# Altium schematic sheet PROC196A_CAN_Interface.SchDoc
size 431 x 279 mm; Date: Not shown in title block; ApprovedBy: Not shown in title block; CheckedBy: Not shown in title block; Author: Not shown in title block; CompanyName: Not shown in title block; Engineer: Not shown in title block; Organization: Not shown in title block; Address1: Not shown in title block; Address2: Not shown in title block; Address3: Not shown in title block; Address4: Not shown in title block; DocumentNumber: 22; Revision: Use project parameter SCH_Rev; SheetNumber: 22; SheetTotal: 25; PageSetup: Record=PageOptions¦CenterHorizontal=True¦CenterVertical=True¦PrintScale=1.00¦XCorrection=1.00¦YCorrection=1.00¦PrintKind=0¦BorderSize=5000000¦LeftOffset=0¦BottomOffset=0¦Orientation=2¦PaperLength=1000¦PaperWidth=1000¦Scale=100¦PaperSource=15¦PrintQuality=600¦MediaType=1¦DitherType=10¦PaperKind=Letter¦PrintScaleMode=1
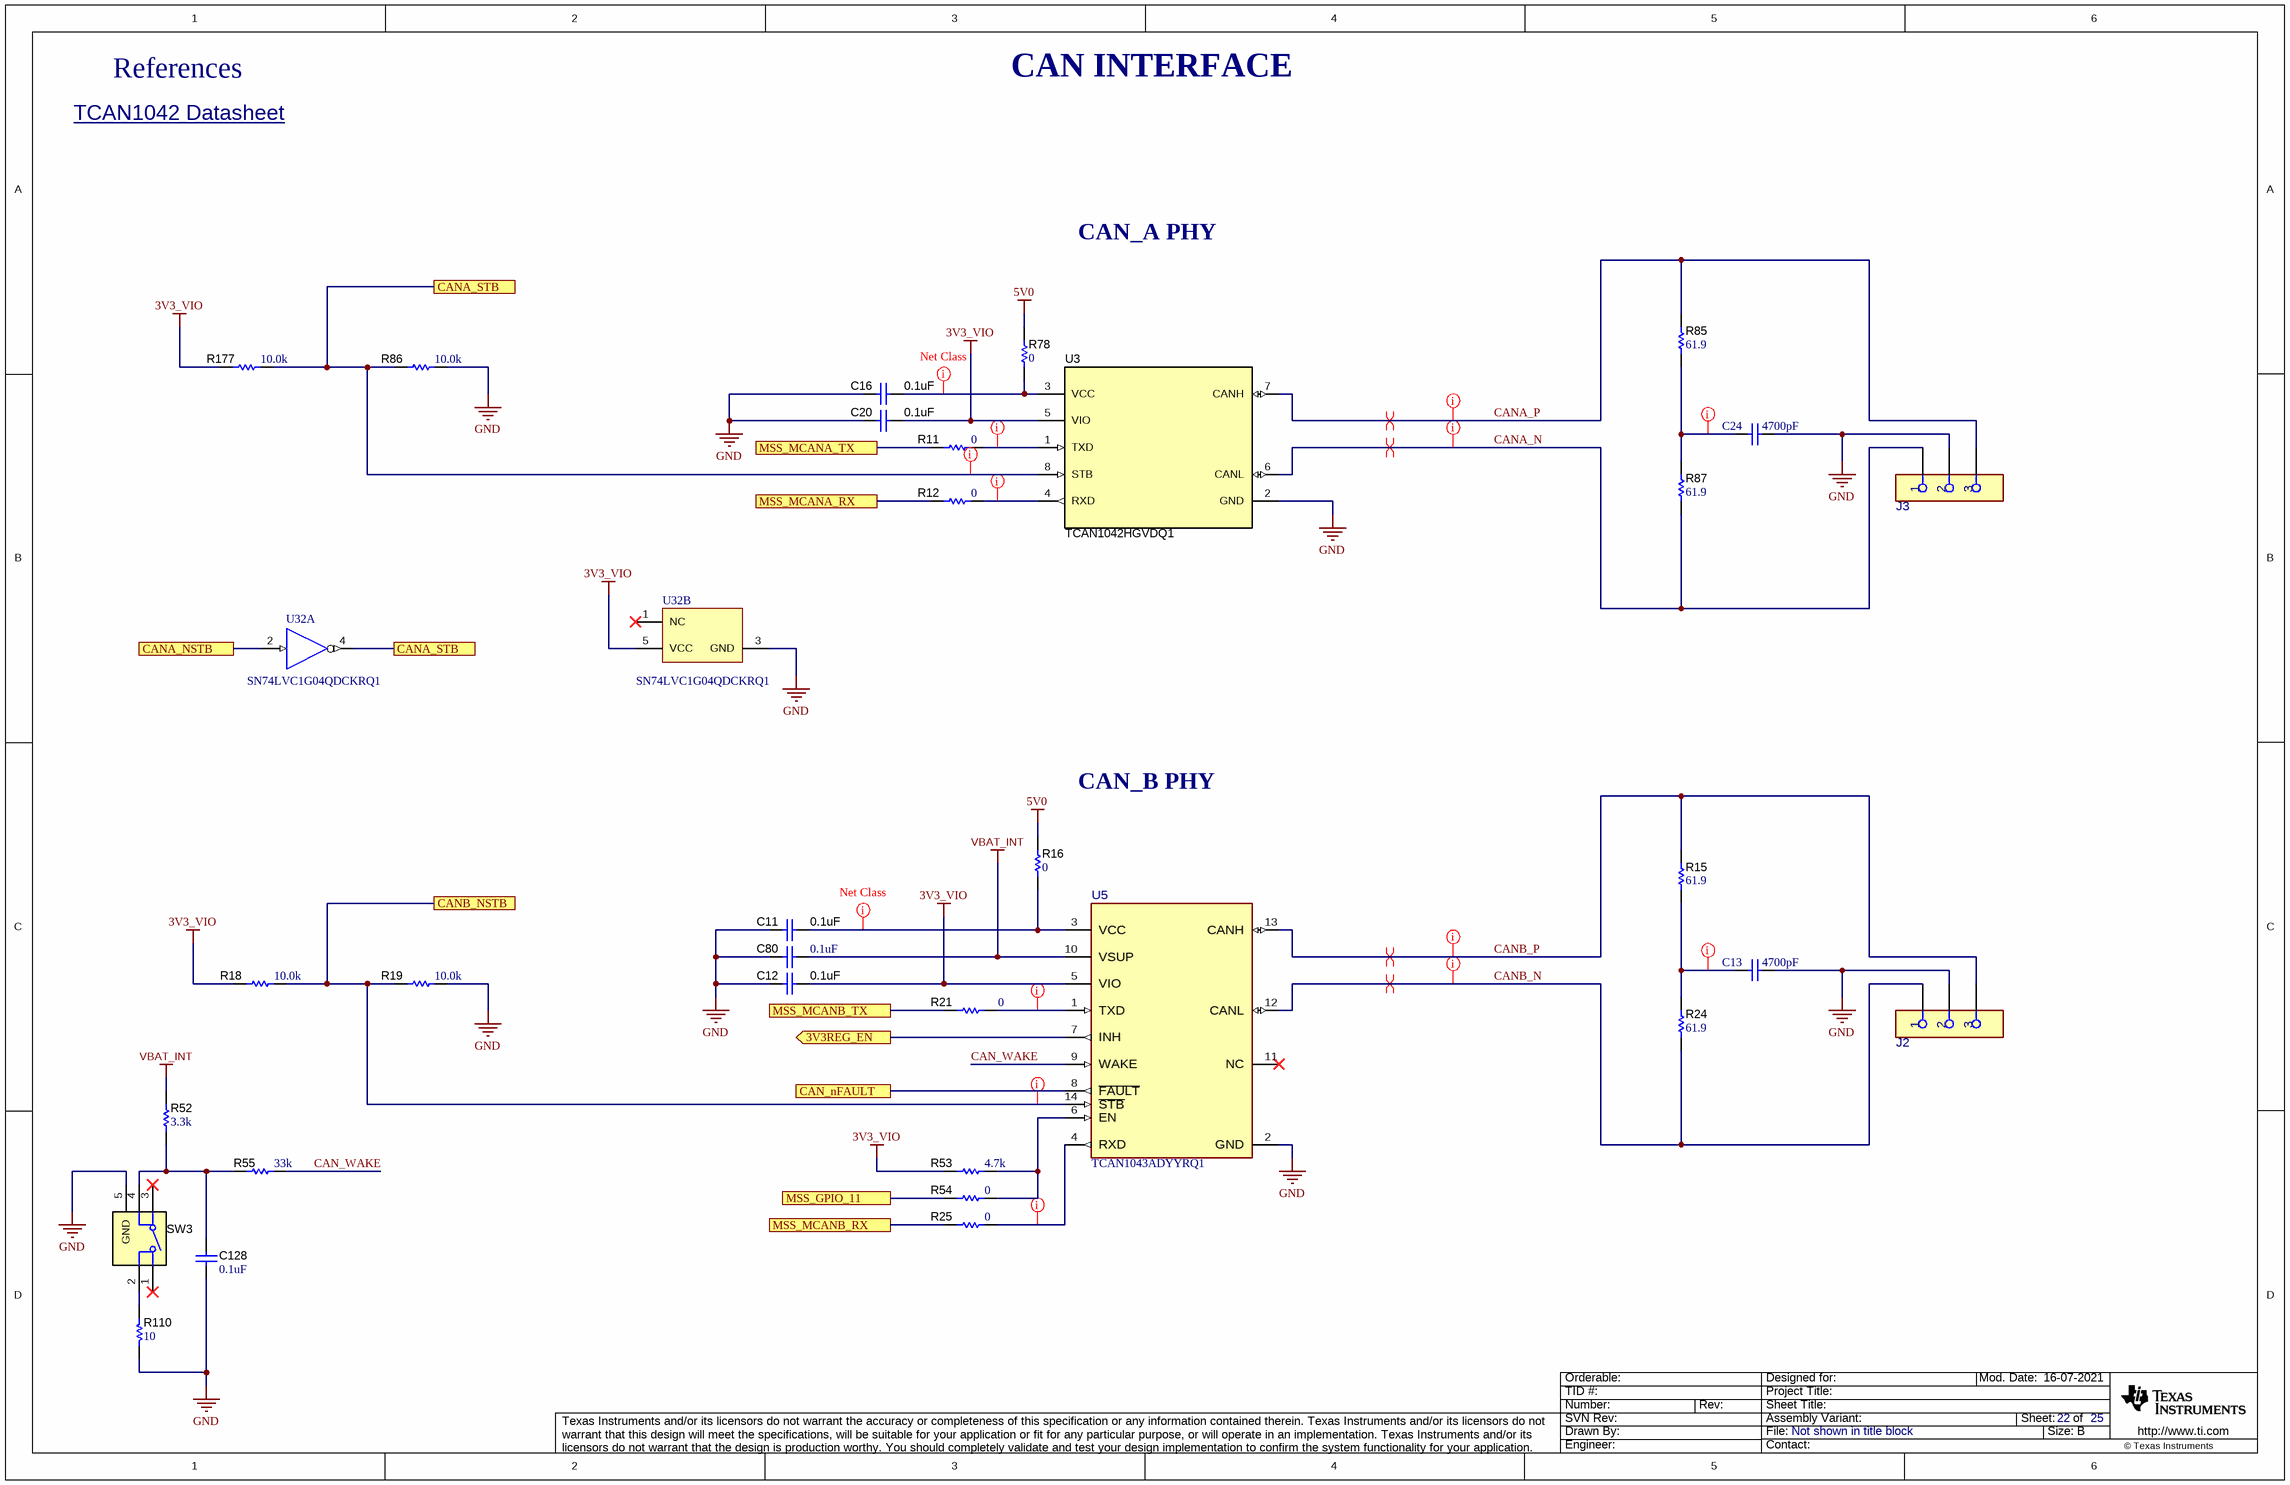
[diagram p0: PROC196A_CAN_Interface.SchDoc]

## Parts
C11  ValueDisplayed: 0.1uF  [0402L]  (hidden comment: GCM155R71C104KA55D)
C12  ValueDisplayed: 0.1uF  [0402L]  (hidden comment: GCM155R71C104KA55D)
C13  ValueDisplayed: 4700pF  [0402L]  (hidden comment: GCM155R71H472KA37D)
C16  ValueDisplayed: 0.1uF  [0402L]  (hidden comment: GCM155R71C104KA55D)
C20  ValueDisplayed: 0.1uF  [0402L]  (hidden comment: GCM155R71C104KA55D)
C24  ValueDisplayed: 4700pF  [0402L]  (hidden comment: GCM155R71H472KA37D)
C80  ValueDisplayed: 0.1uF  [0402L]  (hidden comment: CGA2B3X7R1H104K050BB)
C128  ValueDisplayed: 0.1uF  [0402L]  (hidden comment: CGA2B3X7R1H104K050BB)
J2  OSTTF030161  [FP-OSTTF030161_PTH_TERMINAL_BLOCK-MFG]  (value not drawn)
J3  OSTTF030161  [FP-OSTTF030161_PTH_TERMINAL_BLOCK-MFG]  (value not drawn)
R11  value 0  [0402L]  (hidden comment: ERJ-2GE0R00X)
R12  ValueDisplayed: 0  [0402L]  (hidden comment: ERJ-2GE0R00X)
R15  ValueDisplayed: 61.9  [0402L]  (hidden comment: CRCW040261R9FKED)
R16  ValueDisplayed: 0  [0402L]  (hidden comment: ERJ-2GE0R00X)
R18  ValueDisplayed: 10.0k  [0402L]  (hidden comment: CRCW040210K0FKED)
R19  ValueDisplayed: 10.0k  [0402L]  (hidden comment: CRCW040210K0FKED)
R21  value 0  [0402L]  (hidden comment: ERJ-2GE0R00X)
R24  ValueDisplayed: 61.9  [0402L]  (hidden comment: CRCW040261R9FKED)
R25  ValueDisplayed: 0  [0402L]  (hidden comment: ERJ-2GE0R00X)
R52  ValueDisplayed: 3.3k  [0402L]  (hidden comment: CRCW04023K30JNED)
R53  ValueDisplayed: 4.7k  [0402L]  (hidden comment: CRCW04024K70JNED)
R54  ValueDisplayed: 0  [0402L]  (hidden comment: ERJ-2GE0R00X)
R55  ValueDisplayed: 33k  [0402L]  (hidden comment: CRCW040233K0JNED)
R78  ValueDisplayed: 0  [0402L]  (hidden comment: ERJ-2GE0R00X)
R85  ValueDisplayed: 61.9  [0402L]  (hidden comment: CRCW040261R9FKED)
R86  ValueDisplayed: 10.0k  [0402L]  (hidden comment: CRCW040210K0FKED)
R87  ValueDisplayed: 61.9  [0402L]  (hidden comment: CRCW040261R9FKED)
R110  ValueDisplayed: 10  [0402L]  (hidden comment: CRCW040210R0JNED)
R177  ValueDisplayed: 10.0k  [0402L]  (hidden comment: CRCW040210K0FKED)
SW3  KMR243GLFG  [SW_KMR243GLFG]  (value not drawn)
U3  TCAN1042HGVDQ1  [D0008A_L]
U5  TCAN1043ADYYRQ1  [DYY0014A-MFG]
U32  SN74LVC1G04QDCKRQ1  [DCK0005A_N]  (parts A,B of 2)

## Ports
3V3REG_EN (out), CAN_nFAULT, CANA_NSTB, CANA_STB, CANB_NSTB, MSS_GPIO_11, MSS_MCANA_RX, MSS_MCANA_TX, MSS_MCANB_RX, MSS_MCANB_TX

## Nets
3V3_VIO: C12.2 C20.2 R18.1 R53.1 R177.1 U3.5(VIO) U5.5(VIO) U32.5(VCC)
5V0: R16.2 R78.2
GND: C11.1 C12.1 C13.1 C16.1 C20.1 C24.1 C80.2 C128.2 J2.2 J3.2 R19.2 R86.2 R110.1 SW3.5(GND) U3.2(GND) U5.2(GND) U32.3(GND)
VBAT_INT: C80.1 R52.2 U5.10(VSUP)
3V3REG_EN: U5.7(INH) ; port 3V3REG_EN
CAN_nFAULT: U5.8(~{FAULT}) ; port CAN_nFAULT
CAN_WAKE: R55.1 U5.9(WAKE)
CANA_N: J3.1 R87.1 U3.6(CANL)
CANA_NSTB: U32.2(A) ; port CANA_NSTB
CANA_P: J3.3 R85.2 U3.7(CANH)
CANA_STB: R86.1 R177.2 U3.8(STB) U32.4(Y) ; port CANA_STB
CANB_N: J2.1 R24.1 U5.12(CANL)
CANB_NSTB: R18.2 R19.1 U5.14(~{STB}) ; port CANB_NSTB
CANB_P: J2.3 R15.2 U5.13(CANH)
MSS_GPIO_11: R54.1 ; port MSS_GPIO_11
MSS_MCANA_RX: R12.1 ; port MSS_MCANA_RX
MSS_MCANA_TX: R11.1 ; port MSS_MCANA_TX
MSS_MCANB_RX: R25.1 ; port MSS_MCANB_RX
MSS_MCANB_TX: R21.1 ; port MSS_MCANB_TX
NetC11_2: C11.2 R16.1 U5.3(VCC)
NetC13_2: C13.2 R15.1 R24.2
NetC16_2: C16.2 R78.1 U3.3(VCC)
NetC24_2: C24.2 R85.1 R87.2
NetC128_1: C128.1 R52.1 R55.2 SW3.4
NetR11_2: R11.2 U3.1(TXD)
NetR12_2: R12.2 U3.4(RXD)
NetR21_2: R21.2 U5.1(TXD)
NetR25_2: R25.2 U5.4(RXD)
NetR53_2: R53.2 R54.2 U5.6(EN)
NetR110_2: R110.2 SW3.2

Not connected (* = marked no-connect by the designer): SW3 1* 3*; U5 11(NC)*; U32 1(NC)*

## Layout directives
net class CAN: CANA_STB, CANB_NSTB, NetR11_2, NetR12_2, NetR21_2, NetR25_2
net class CAN; net class CAN_DIFF: CANA_N, CANA_P, CANB_N, CANB_P
net class CAN; net class PWR: NetC13_2, NetC24_2
net class PWR: NetC11_2, NetC16_2
differential pair: CANA_N, CANA_P, CANB_N, CANB_P

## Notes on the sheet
- References
- CAN INTERFACE
- TCAN1042 Datasheet <http://www.ti.com/lit/ds/symlink/tcan1042gv-q1.pdf>
- CAN_A PHY
- CAN_B PHY

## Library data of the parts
C11 C12 C16 C20 = CMP-0006351-2: CAP, CERM, 0.1 uF, 16 V, +/- 10%, X7R, 0402; Manufacturer: MuRata; TaMin_C: -55°C; Polarized: N; SizeAreaWB_mm2: 3; Value1: Unknown; U/M: EA; Value: 0.1uF; TaMax_C: 125°C; SizeZ_mm: 0.6; SizeX_mm: 1; SizeY_mm: 0.5; Cap_Case: 0402; Value2: 16V; Cap_F: 100nF; AEC Category: Q200
C13 C24 = CMP-0006361-2: CAP, CERM, 4700 pF, 50 V, +/- 10%, X7R, AEC-Q200 Grade 1, 0402; Manufacturer: MuRata; TaMin_C: -55°C; Polarized: N; SizeAreaWB_mm2: 3; Value1: Unknown; U/M: EA; Value: 4700pF; TaMax_C: 125°C; SizeZ_mm: 0.6; SizeX_mm: 1; SizeY_mm: 0.5; Cap_Case: 0402; Value2: 50V; AEC Qualified: Y; Cap_F: 4.7nF; AEC Category: Q200
C80 C128 = CMP-0006325-2: CAP, CERM, 0.1 uF, 50 V, +/- 10%, X7R, AEC-Q200 Grade 1, 0402; Manufacturer: TDK; TaMin_C: -55°C; ESR_ohm: 0.039064; Polarized: N; SizeAreaWB_mm2: 3; Value1: 0.039064 ohm; U/M: EA; Value: 0.1uF; TaMax_C: 125°C; SizeZ_mm: 0.6; SizeX_mm: 1; SizeY_mm: 0.5; Cap_Case: 0402; Value2: 50V; AEC Qualified: Y; Cap_F: 100nF; IRMS_A: 8.14669dA; AEC Category: Q200
J2 J3 = CMP-0091742-1: 3 Position Wire to Board Terminal Block Vertical with Board 0.138" (3.50mm) Through Hole; Manufacturer: On Shore Technology; Voltage_V: 150V; Row_Count: 1; DUT-Pitch_mm: 3.5mm; Current_A: 10A; Min Wire Gauge: 30; ContactFinish: Tin; AEC Qualified: No; Conn Gender: Female; Is Female: yes; Max Wire Gauge: 16; SizeZ_mm: 7.3mm
R11 R21 = CMP-0026992-3: RES, 0, 5%, 0.1 W, AEC-Q200 Grade 0, 0402; Manufacturer: Panasonic; Power_W: 100mW; TempCo: 600 ppm/C; Value_Code: 0000; EIA_Code: E24; SizeX_mm: 1; SizeY_mm: 0.5; SizeZ_mm: 0.6; Value2: 0.1W; AEC Qualified: Y; VDC_V: 50V; AEC Category: Q200; SizeAreaWB_mm2: 3
R12 R16 R25 R54 R78 = CMP-0026992-3: RES, 0, 5%, 0.1 W, AEC-Q200 Grade 0, 0402; Manufacturer: Panasonic; Power_W: 100mW; TempCo: 600 ppm/C; Value_Code: 0000; Value: 0; EIA_Code: E24; SizeX_mm: 1; SizeY_mm: 0.5; SizeZ_mm: 0.6; Value2: 0.1W; AEC Qualified: Y; VDC_V: 50V; AEC Category: Q200; SizeAreaWB_mm2: 3
R15 R24 R85 R87 = CMP-0026491-2: RES, 61.9, 1%, 0.063 W, AEC-Q200 Grade 0, 0402; Manufacturer: Vishay-Dale; Power_W: 63mW; TempCo: 100 ppm/C; Value_Code: 61R9; Value: 61.9; EIA_Code: E96; SizeX_mm: 1; SizeY_mm: 0.5; SizeZ_mm: 0.6; Value2: 0.063W; AEC Qualified: Y; VDC_V: 50V; AEC Category: Q200; AEC Grade: 0
R18 R19 R86 R177 = CMP-0025958-3: RES, 10.0 k, 1%, 0.063 W, AEC-Q200 Grade 0, 0402; Manufacturer: Vishay-Dale; Power_W: 63mW; TempCo: 100 ppm/C; Value_Code: 10k0; Value: 10.0k; EIA_Code: E96; Res_ohm: 10k; SizeX_mm: 1; SizeY_mm: 0.5; SizeZ_mm: 0.6; Value2: 0.063W; AEC Qualified: Y; VDC_V: 50V; AEC Category: Q200; AEC Grade: 0
R52 = CMP-0026918-5: RES, 3.3 k, 5%, 0.063 W, AEC-Q200 Grade 0, 0402; Manufacturer: Vishay-Dale; Power_W: 63mW; TempCo: 200 ppm/C; Value_Code: 3k30; Value: 3.3k; EIA_Code: E24; SizeX_mm: 1; SizeY_mm: 0.5; SizeZ_mm: 0.6; Value2: 0.063W; AEC Qualified: Y; VDC_V: 50V; AEC Category: Q200; AEC Grade: 0
R53 = CMP-0026938-5: RES, 4.7 k, 5%, 0.063 W, AEC-Q200 Grade 0, 0402; Manufacturer: Vishay-Dale; Power_W: 63mW; TempCo: 200 ppm/C; Value_Code: 4k70; Value: 4.7k; EIA_Code: E24; SizeX_mm: 1; SizeY_mm: 0.5; SizeZ_mm: 0.6; Value2: 0.063W; AEC Qualified: Y; VDC_V: 50V; AEC Category: Q200; AEC Grade: 0
R55 = CMP-0026907-3: RES, 33 k, 5%, 0.063 W, AEC-Q200 Grade 0, 0402; Manufacturer: Vishay-Dale; Power_W: 63mW; TempCo: 200 ppm/C; Value_Code: 33k0; Value: 33k; EIA_Code: E24; SizeX_mm: 1; SizeY_mm: 0.5; SizeZ_mm: 0.6; Value2: 0.063W; AEC Qualified: Y; VDC_V: 50V; AEC Category: Q200; AEC Grade: 0
R110 = CMP-0026827-3: RES, 10, 5%, 0.063 W, AEC-Q200 Grade 0, 0402; Manufacturer: Vishay-Dale; Power_W: 63mW; TempCo: 200 ppm/C; Value_Code: 10R0; Value: 10; EIA_Code: E24; SizeX_mm: 1; SizeY_mm: 0.5; SizeZ_mm: 0.6; Value2: 0.063W; AEC Qualified: Y; VDC_V: 50V; AEC Category: Q200; AEC Grade: 0
SW3 = CMP-0002325-1: Switch, SPST-NO, Off-Mom, 0.01 A, 32 VDC, SMD; Manufacturer: C&K Components; CurrentRating_mA: 10A; PositionCount: 1; SizeX_mm: 4.6; SizeY_mm: 2.8; SizeZ_mm: 1.9; SizeArea_mm2: 12.88; VDC_V: 32V; SizeAreaWB_mm2: 21.28
U3 = CMP-0075992-1: Automotive Fault Protected CAN Transceiver With Flexible Data-Rate, D0008A (SOIC-8); Manufacturer: Texas Instruments; Alternate PartNumber: TCAN1042HGVDRQ1; SizeAreaWB_mm2: 56.58; SizeArea_mm2: 30.38; SizeZ_mm: 1.75; SizeY_mm: 6.2; U/M: EA; CompType: IC; SizeX_mm: 4.9
U5 = CMP-0089855-1: Low-Power Fault Protected CAN FD Transceiver with INH and WAKE; Manufacturer: Texas Instruments; Max Supply Voltage: 28V; Standoff Height: 0mm; Min Supply Voltage: 1.7V; AEC Grade: Grade 1; SizeZ_mm: 1.1mm; TJmax_C: +165°C; AEC Qualified: Yes
U32 = CMP-0051661-3: Automotive Catalog Single Inverter, DCK0005A, LARGE T&R; Manufacturer: Texas Instruments; Generic Part Number: SN74LVC1G04-Q1; Logic: Inverting; Input Type: CMOS/TTL; 3-State Output: No; Voltage(Nom)(V): 1.8,2.5,3.3,5; tpd @ Nom Voltage(Max)(ns): 7.5,5.2,4.2,3.7; Sub-Family: Inverting Buffer/Driver; Bits(#): 1; VCC(Min)(V): 1.65; F @ Nom Voltage(Max)(Mhz): 150; ICC @ Nom Voltage(Max)(mA): 0.01; Technology Family: LVC; Output Drive (IOL/IOH)(Max)(mA): 32/-32; Output Type: CMOS; VCC(Max)(V): 5.5; AEC Category: Q200; AEC Qualified: Y; CompType: IC; SizeAreaWB_mm2: 9.3; SizeArea_mm2: 4.2; SizeX_mm: 2.1; SizeY_mm: 2.0; SizeZ_mm: 1.1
